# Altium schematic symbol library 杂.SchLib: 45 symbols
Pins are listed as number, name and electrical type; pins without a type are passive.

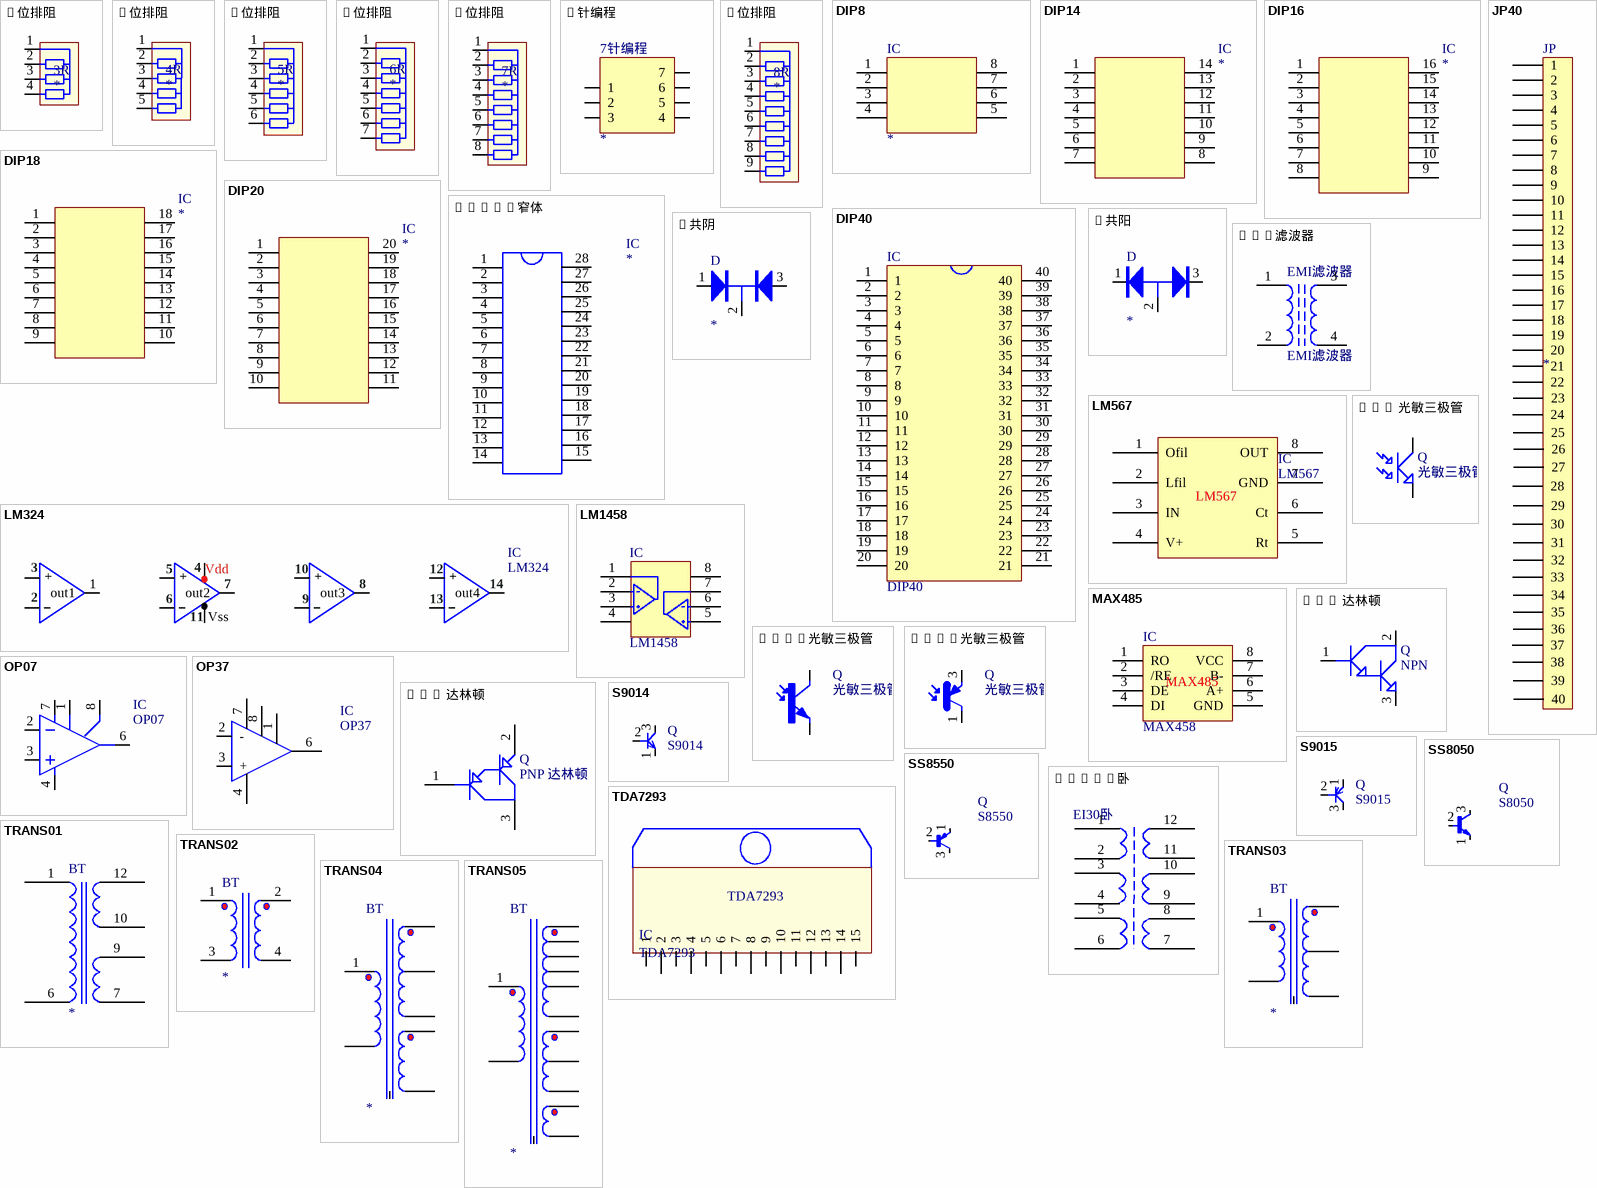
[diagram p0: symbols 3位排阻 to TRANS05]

## 3位排阻
designator 3R
footprint 排阻3位
pins: 1, 2, 3, 4

## 4位排阻
designator 4R
footprint 排阻4位
pins: 1, 2, 3, 4, 5

## 5位排阻
designator 5R
footprint 排阻5位
pins: 1, 2, 3, 4, 5, 6 (oc)

## 6位排阻
designator 6R
footprint 排阻6位
pins: 1, 2, 3, 4, 5, 6 (oc), 7

## 7位排阻
designator 7R
footprint 排阻7位
pins: 1, 2, 3, 4, 5, 6 (oc), 7, 8

## 7针编程
designator 7针编程
footprint 7针编程 (Footprint not found)
pins: 1, 2, 3, 4, 5, 6, 7

## 8位排阻
designator 8R
footprint 排阻8位
pins: 1, 2, 3, 4, 5, 6 (oc), 7, 8, 9

## DIP8
designator IC
footprint DIP8
footprint DIP8插座
footprint SOP8
pins: 1, 2, 3, 4, 5, 6, 7, 8

## DIP14
designator IC
footprint DIP14插座
footprint DIP14
footprint SOP14
footprint SOIC14
pins: 1, 2, 3, 4, 5, 6, 7, 8, 9, 10, 11, 12, 13, 14

## DIP16
designator IC
footprint DIP16插座
footprint DIP16
footprint SOP16
footprint SOIC16
pins: 1, 2, 3, 4, 5, 6, 7, 8, 9, 10, 11, 12, 13, 14, 15, 16

## DIP18
designator IC
footprint DIP18插座
footprint DIP18
footprint SOP18
footprint SOIC18
pins: 1, 2, 3, 4, 5, 6, 7, 8, 9, 10, 11, 12, 13, 14, 15, 16, 17, 18

## DIP20
designator IC
footprint DIP20插座
footprint DIP20
footprint SOP20
footprint SOIC20
pins: 1, 2, 3, 4, 5, 6, 7, 8, 9, 10, 11, 12, 13, 14, 15, 16, 17, 18, 19, 20

## DIP28窄体
designator IC
footprint DIP28窄体
footprint DIP28窄体插座
pins: 1, 2, 3, 4, 5, 6, 7, 8, 9, 10, 11, 12, 13, 14, 15, 16, 17, 18, 19, 20, 21, 22, 23, 24, 25, 26, 27, 28

## DIP40
designator IC
footprint DIP40
footprint DIP40插座
footprint 锁紧插座-40
pins: 1, 2, 3, 4, 5, 6, 7, 8, 9, 10, 11, 12, 13, 14, 15, 16, 17, 18, 19, 20, 21, 22, 23, 24, 25, 26, 27, 28, 29, 30, 31, 32, 33, 34, 35, 36, 37, 38, 39, 40

## D共阳
designator D
footprint TO-220立
pins: 1 K1, 2 A, 3 K2

## D共阴
designator D
footprint TO-220立
pins: 1 A1, 2 K, 3 A2

## EMI滤波器
designator EMI滤波器
footprint EMI滤波器 (18mmX16mm)
pins: 1, 2, 3, 4

## JP40
designator JP
footprint P40-5.08; pin to pad 1>0 2>1 3>2 4>3 5>4 6>5 7>6 8>7 9>8 10>9 11>10 12>11 13>12 14>13 15>14 16>15 17>16 18>17 19>18 20>19 21>20 22>21 23>22 24>23 25>24 26>25 27>26 28>27 29>28 30>29 31>30 32>31 33>32 34>33 35>34 36>35 37>36 38>37 39>38 40>39
pins: 1, 2, 3, 4, 5, 6, 7, 8, 9, 10, 11, 12, 13, 14, 15, 16, 17, 18, 19, 20, 21, 22, 23, 24, 25, 26, 27, 28, 29, 30, 31, 32, 33, 34, 35, 36, 37, 38, 39, 40

## LM324
designator IC
footprint DIP14
footprint DIP14插座
footprint SOP14
footprint SOIC14
pins: 1 out1, 2, 3, 4, 5, 6, 7 out2, 8 out3, 9, 10, 11, 12, 13, 14 out4

## LM567
designator IC
footprint DIP8
footprint SOP8
footprint SOIC8
pins: 1 Ofil, 2 Lfil, 3 IN, 4 V+, 5 Rt, 6 Ct, 7 GND, 8 OUT

## LM1458
designator IC
footprint DIP8
footprint SOP8
footprint SOIC8
pins: 1, 2, 3, 4, 5, 6, 7, 8

## MAX485
designator IC, comment MAX458
footprint DIP8
footprint DIP8插座
footprint SOP8
footprint SOIC8
pins: 1 RO, 2 /RE, 3 DE, 4 DI, 5 GND, 6 A+, 7 B-, 8 VCC

## NPN 光敏三极管
designator Q, comment 光敏三极管
footprint TO-46; pin to pad 2>3
pins: 1 C, 2 E

## NPN 达林顿
designator Q, comment NPN
NPN 达林顿
footprint TO-220立
pins: 1 B, 2 C, 3 E

## NPN-光敏三极管
designator Q, comment 光敏三极管
footprint TO-46; pin to pad 2>3
pins: 1 C, 2 E

## OP07
designator IC
footprint DIP8
footprint SOIC8
footprint SOP8
pins: 1, 2, 3, 4, 6, 7, 8

## OP37
designator IC
footprint DIP8
footprint SOIC8
footprint SOP8
pins: 1, 2 -, 3 +, 4 VW, 6, 7 VC, 8

## PNP 达林顿
designator Q
footprint TO-220立
pins: 1 B, 2 E, 3 C

## PNP-光敏三极管
designator Q, comment 光敏三极管
footprint TO-46
pins: 1 C, 3 E

## S9014
designator Q
footprint TO-92B
footprint TO-92D1
footprint SOT23-3 (SOT-23; 3 Leads; Body 3.0 x 2.5 mm, inc. leads (LxW max)); pin to pad 1>2 2>1
pins: 1 E, 2 B, 3 C

## S9015
designator Q
footprint TO-92B
footprint TO-92D1
footprint SOT23-3 (SOT-23; 3 Leads; Body 3.0 x 2.5 mm, inc. leads (LxW max)); pin to pad 1>2 2>1
pins: 1 E, 2 B, 3 C

## SS8050
designator Q, comment S8050
NPN三极管
footprint TO-92B
footprint TO-92C
footprint SOT23-3 (SOT-23; 3 Leads; Body 3.0 x 2.5 mm, inc. leads (LxW max)); pin to pad 1>2 2>1
pins: 1 E, 2 B, 3 C

## SS8550
designator Q, comment S8550
PNP 三极管
footprint TO-92B
footprint TO-92C
footprint SOT23-3 (SOT-23; 3 Leads; Body 3.0 x 2.5 mm, inc. leads (LxW max)); pin to pad 1>2 2>1
pins: 1 E, 2 B, 3 C

## TDA7293
designator IC
集成功放
footprint TDA7293 (集成功放)
pins: 1, 2, 3, 4, 5, 6, 7, 8, 9, 10, 11, 12, 13, 14, 15

## TEI30卧
designator EI30卧  (value not drawn)
footprint TEI30卧 (EI30卧  34mmX30mm  12P)
pins: 1, 2, 3, 4, 5, 6, 7, 8, 9, 10, 11, 12

## TRANS01
designator BT
footprint TEI33 (EI33)
pins: 1, 6, 7, 9, 10, 12

## TRANS02
designator BT
pins: 1, 2, 3, 4

## TRANS03
designator BT
pins: 1, 2, 3, 4, 5, 6

## TRANS04
designator BT
pins: 1, 2, 3, 4, 5, 6, 7, 8

## TRANS05
designator BT
pins: 1, 2, 3, 4, 5, 6, 7, 8, 9, 10, 11, 12, 13, 14

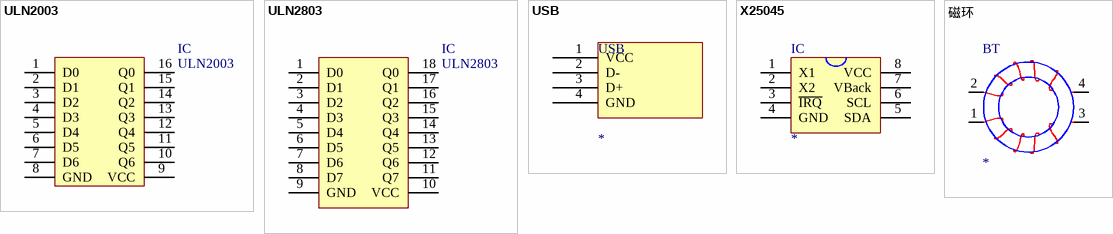
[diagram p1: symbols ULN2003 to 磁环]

## ULN2003
designator IC
footprint DIP16
footprint DIP16插座
footprint SOP16
pins: 1 D0, 2 D1, 3 D2, 4 D3, 5 D4, 6 D5, 7 D6, 8 GND, 9 VCC, 10 Q6, 11 Q5, 12 Q4, 13 Q3, 14 Q2, 15 Q1, 16 Q0

## ULN2803
designator IC
footprint DIP18插座
footprint DIP18
footprint SOP18
pins: 1 D0, 2 D1, 3 D2, 4 D3, 5 D4, 6 D5, 7 D6, 8 D7, 9 GND, 10 VCC, 11 Q7, 12 Q6, 13 Q5, 14 Q4, 15 Q3, 16 Q2, 17 Q1, 18 Q0

## USB
designator USB
footprint USB阳头
footprint USB阴头
pins: 1 VCC, 2 D-, 3 D+, 4 GND

## X25045
designator IC
footprint DIP8
footprint SOP8
footprint SOIC8
pins: 1 X1, 2 X2, 3 ~{IRQ}, 4 GND, 5 SDA, 6 SCL, 7 VBack, 8 VCC

## 磁环
designator BT
footprint 磁环 (外径20.32mm脚距25.4mm)
footprint 磁环1 (外径12mm脚距17.78mm); pin to pad 2>3 4>2
footprint 磁环2 (外径11mm脚距12mm)
pins: 1, 2, 3, 4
